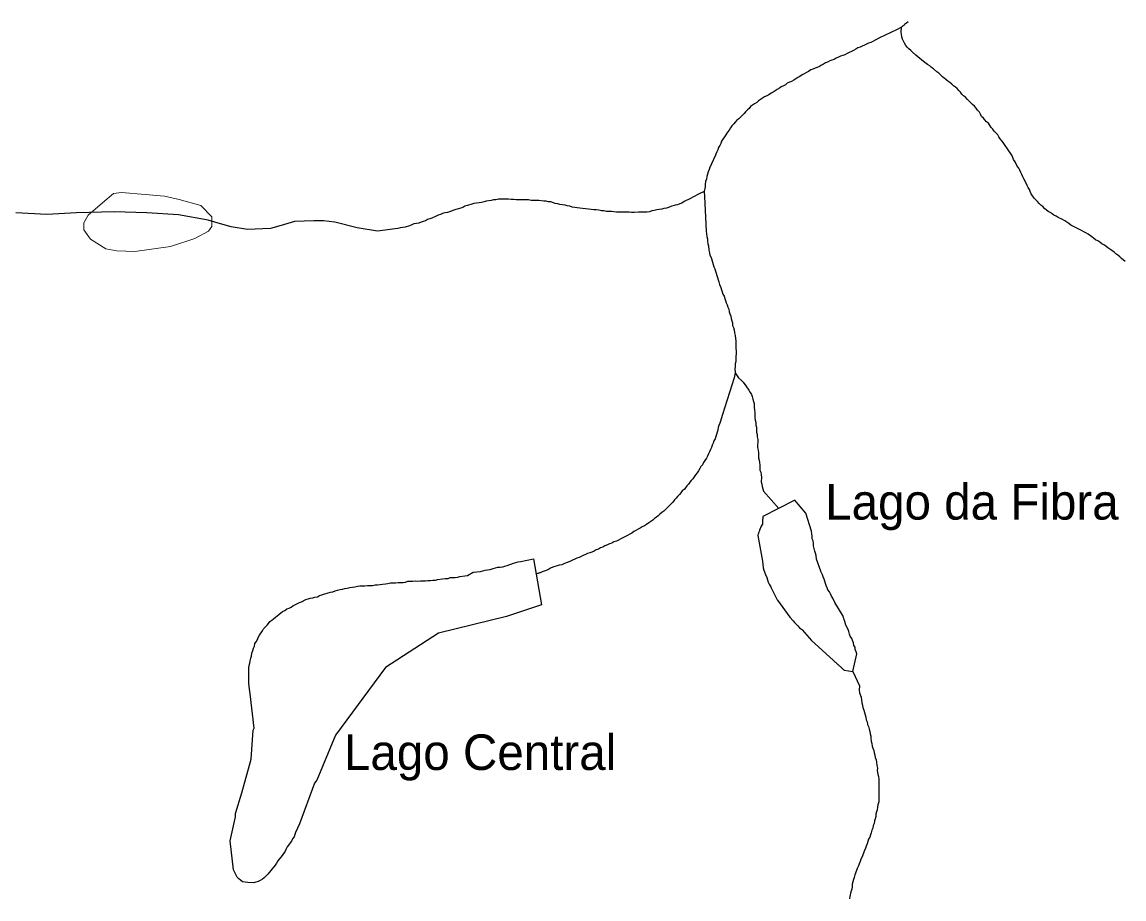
# Model space of a CAD drawing. Extents: x 785.9 to 812.4, y 7674.9 to 7703.1.
# Drawn here: x 791.421 to 793.899, y 7678.493 to 7680.465 of the extents above; entities that cross this region are included whole.
import ezdxf

# ---------------------------------------------------------------- set-up
doc = ezdxf.new("R2010")
doc.units = 0
doc.header["$LTSCALE"] = 0.04
doc.linetypes.add('LONG_DASHED', pattern=[7.5, 6, -1.5])
doc.linetypes.add('SHORT_DASHED', pattern=[2.7, 1.5, -1.2])
for name, color, linetype, lineweight in [('2', 7, 'Continuous', 25), ('21', 7, 'SHORT_DASHED', 13), ('3', 7, 'LONG_DASHED', 25), ('7', 7, 'Continuous', 25)]:
    doc.layers.add(name, color=color, linetype=linetype, lineweight=lineweight)
doc.layers.add('61', color=7, linetype='Continuous')

msp = doc.modelspace()

# ---------------------------------------------------------------- linework, layer by layer
at = {"layer": '2'}
msp.add_line((792.5718, 7679.2584), (792.5898, 7679.1547), dxfattribs=at)
for points in [[(791.94, 7679.0524), (791.9416, 7679.0573), (791.9441, 7679.0621), (791.9449, 7679.0678), (791.9481, 7679.0718), (791.9505, 7679.0767), (791.9522, 7679.0815), (791.9554, 7679.0864), (791.9619, 7679.0961), (791.9643, 7679.101), (791.9724, 7679.109), (791.9756, 7679.1131), (791.9789, 7679.1171), (791.9829, 7679.1204), (791.987, 7679.1236), (791.991, 7679.1268), (791.9991, 7679.1333), (792.0031, 7679.1366), (792.0072, 7679.1398), (792.012, 7679.1422), (792.0169, 7679.1455), (792.0217, 7679.1471), (792.0266, 7679.1495), (792.0306, 7679.1527), (792.0452, 7679.16), (792.0501, 7679.1616), (792.0598, 7679.1665), (792.0646, 7679.1681), (792.0695, 7679.1697), (792.0751, 7679.1705), (792.08, 7679.1722), (792.0857, 7679.173), (792.0905, 7679.1754), (792.0954, 7679.177), (792.1002, 7679.1786), (792.1099, 7679.1819), (792.1148, 7679.1835), (792.1205, 7679.1843), (792.1253, 7679.1859), (792.131, 7679.1875), (792.1366, 7679.1891), (792.1423, 7679.19), (792.1472, 7679.1916), (792.1528, 7679.1924), (792.1585, 7679.194), (792.1642, 7679.1948), (792.1698, 7679.1956), (792.1755, 7679.1964), (792.1811, 7679.1972), (792.1925, 7679.1972), (792.1981, 7679.1981), (792.2095, 7679.1981), (792.2151, 7679.1997), (792.2208, 7679.1997), (792.2265, 7679.2005), (792.2321, 7679.2013), (792.2386, 7679.2021), (792.2443, 7679.2029), (792.2499, 7679.2045), (792.2612, 7679.2045), (792.2669, 7679.2053), (792.2782, 7679.2053), (792.2839, 7679.2061), (792.2888, 7679.2078), (792.3001, 7679.2078), (792.3058, 7679.2086), (792.3114, 7679.2078), (792.3171, 7679.2086), (792.3284, 7679.2086), (792.3341, 7679.2094), (792.3397, 7679.2094), (792.3454, 7679.2102), (792.3511, 7679.2102), (792.3559, 7679.2118), (792.3672, 7679.2134), (792.3729, 7679.2142), (792.3794, 7679.2142), (792.3842, 7679.2159), (792.3956, 7679.2159), (792.4012, 7679.2167), (792.4061, 7679.2183), (792.4174, 7679.2199), (792.4231, 7679.2207), (792.4359, 7679.2281), (792.4522, 7679.2296), (792.4579, 7679.2312), (792.4627, 7679.2328), (792.4684, 7679.2337), (792.4741, 7679.2345), (792.4805, 7679.2361), (792.4862, 7679.2377), (792.491, 7679.2393), (792.4967, 7679.2393), (792.5024, 7679.2401), (792.5072, 7679.2417), (792.5121, 7679.2434), (792.5266, 7679.2482), (792.5315, 7679.2498), (792.5372, 7679.2515), (792.5428, 7679.2523), (792.5718, 7679.2584)], [(792.5898, 7679.1547), (792.5667, 7679.1476), (792.5667, 7679.1476), (792.5105, 7679.1288), (792.5105, 7679.1288), (792.3582, 7679.0913), (792.3582, 7679.0913), (792.2387, 7679.0139), (792.2387, 7679.0139), (792.1262, 7678.8614), (792.1262, 7678.8614), (792.084, 7678.7605), (792.0793, 7678.7535), (792.0452, 7678.6624)], [(791.9344, 7678.9545), (791.9327, 7678.965), (791.9311, 7678.9788), (791.9311, 7679.0128), (791.9319, 7679.0184), (791.9335, 7679.0233), (791.9344, 7679.0289), (791.936, 7679.0346), (791.9376, 7679.0395), (791.9384, 7679.0459), (791.94, 7679.0524)], [(791.8966, 7678.5588), (791.8966, 7678.5588), (791.8895, 7678.6244), (791.8895, 7678.6244), (791.9012, 7678.6784), (791.9012, 7678.6854), (791.9153, 7678.7324), (791.9153, 7678.7324), (791.9364, 7678.8074), (791.9364, 7678.8074), (791.9411, 7678.8731), (791.9434, 7678.8778), (791.9344, 7678.9545)], [(792.0452, 7678.6624), (792.0363, 7678.643), (792.0347, 7678.6381), (792.0331, 7678.6333), (792.0298, 7678.6284), (792.0274, 7678.6236), (792.0242, 7678.6195), (792.0209, 7678.6147), (792.0177, 7678.6106), (792.0153, 7678.6058), (792.0128, 7678.6009), (792.0064, 7678.5912), (792.0031, 7678.5871), (791.9999, 7678.5831), (791.9967, 7678.5791), (791.9934, 7678.5742), (791.9902, 7678.5693), (791.9837, 7678.5613), (791.9805, 7678.5572), (791.9772, 7678.5532), (791.974, 7678.5491), (791.97, 7678.5451), (791.9659, 7678.541), (791.9619, 7678.5378), (791.957, 7678.5346), (791.9522, 7678.5329), (791.9473, 7678.5313), (791.9424, 7678.5297), (791.9294, 7678.5306), (791.9174, 7678.5321), (791.9125, 7678.5354), (791.9085, 7678.5386), (791.9052, 7678.5426), (791.8966, 7678.5588)]]:
    msp.add_lwpolyline(points, dxfattribs=at)
at = {"layer": '21'}
msp.add_lwpolyline([(791.6451, 7680.0816), (791.698, 7680.0771), (791.7415, 7680.0738), (791.7744, 7680.066), (791.8234, 7680.0526), (791.8479, 7680.027), (791.8479, 7680.0053), (791.8407, 7679.9947), (791.81, 7679.9785), (791.7554, 7679.9607), (791.6746, 7679.949), (791.6345, 7679.9507), (791.6094, 7679.9551), (791.5749, 7679.9768), (791.5604, 7679.998), (791.5604, 7680.0136), (791.5699, 7680.0309), (791.6022, 7680.0588), (791.6273, 7680.0799)], close=True, dxfattribs=at)
at = {"layer": '3'}
for points in [[(793.2194, 7679.227), (793.2186, 7679.2285), (793.2179, 7679.2299), (793.2177, 7679.2303), (793.2079, 7679.2571), (793.2071, 7679.266), (793.2055, 7679.2709), (793.2039, 7679.2757), (793.2031, 7679.2814), (793.2015, 7679.2871), (793.2015, 7679.2927), (793.2007, 7679.2984), (793.1982, 7679.3032), (793.1982, 7679.3089), (793.1974, 7679.3146), (793.1966, 7679.3202), (793.1837, 7679.3607), (793.1586, 7679.3906), (793.1592, 7679.3899), (793.1227, 7679.3713), (793.0871, 7679.3532), (793.0866, 7679.3421)], [(793.0866, 7679.3421), (793.0866, 7679.3364), (793.0833, 7679.3316), (793.0801, 7679.3227), (793.0795, 7679.3211), (793.079, 7679.3196), (793.0784, 7679.3181), (793.0779, 7679.3166), (793.0773, 7679.3151), (793.0768, 7679.3135), (793.0762, 7679.312), (793.0757, 7679.3105), (793.0866, 7679.2531)], [(793.0866, 7679.2531), (793.0882, 7679.2377), (793.0898, 7679.2328), (793.093, 7679.2231), (793.0963, 7679.2159), (793.0979, 7679.211), (793.0995, 7679.2061), (793.1019, 7679.2013), (793.1044, 7679.1964), (793.106, 7679.1932), (793.1197, 7679.1657), (793.1201, 7679.165)], [(793.1964, 7679.0746), (793.2452, 7679.0306), (793.2452, 7679.0306), (793.2464, 7679.0295), (793.2476, 7679.0284), (793.2488, 7679.0273), (793.25, 7679.0262), (793.2512, 7679.0251), (793.2524, 7679.0241), (793.2536, 7679.023), (793.2548, 7679.0219), (793.256, 7679.0208), (793.2572, 7679.0197), (793.2584, 7679.0186), (793.2596, 7679.0176), (793.2608, 7679.0165), (793.262, 7679.0154), (793.2632, 7679.0143), (793.2644, 7679.0132), (793.2656, 7679.0121), (793.2668, 7679.0111), (793.268, 7679.01), (793.2692, 7679.0089), (793.2704, 7679.0078), (793.2897, 7679.0047), (793.2897, 7679.0047), (793.2986, 7679.0443), (793.297, 7679.0492), (793.2953, 7679.054), (793.2953, 7679.0597), (793.2921, 7679.0637), (793.2913, 7679.0694), (793.2889, 7679.0743), (793.2872, 7679.0791), (793.284, 7679.084), (793.2824, 7679.0888), (793.2808, 7679.0945), (793.2792, 7679.0993), (793.2743, 7679.109), (793.2719, 7679.1171), (793.2711, 7679.1196), (793.2705, 7679.1211), (793.27, 7679.1226), (793.2695, 7679.1242), (793.269, 7679.1257), (793.2685, 7679.1272), (793.268, 7679.1288), (793.2679, 7679.1292), (793.2492, 7679.16), (793.2444, 7679.1697), (793.2419, 7679.1746), (793.2395, 7679.1794), (793.2371, 7679.1843), (793.2338, 7679.1883), (793.2322, 7679.1932), (793.2298, 7679.1981), (793.2282, 7679.2029), (793.2266, 7679.2078), (793.2249, 7679.2126), (793.2233, 7679.2175), (793.2217, 7679.2223), (793.2201, 7679.2256), (793.2194, 7679.227)], [(793.1201, 7679.165), (793.1481, 7679.1268), (793.1554, 7679.1188), (793.1586, 7679.1147), (793.1626, 7679.1115), (793.1659, 7679.1074), (793.1699, 7679.1034), (793.174, 7679.1001), (793.1757, 7679.0984)], [(793.1757, 7679.0984), (793.1757, 7679.0984), (793.1964, 7679.0746)]]:
    msp.add_lwpolyline(points, dxfattribs=at)
at = {"layer": '7'}
for p, q in [((793.3984, 7680.4425), (793.3994, 7680.454)), ((793.0251, 7679.6766), (793.0225, 7679.6654)), ((793.0251, 7679.6766), (793.0327, 7679.6655))]:
    msp.add_line(p, q, dxfattribs=at)
for points in [[(793.3882, 7680.448), (793.3495, 7680.4296), (793.3398, 7680.4247), (793.335, 7680.4215), (793.3301, 7680.419), (793.3253, 7680.4174), (793.3204, 7680.4158), (793.3156, 7680.4134), (793.3107, 7680.411), (793.3059, 7680.4085), (793.301, 7680.4069), (793.2961, 7680.4045), (793.2913, 7680.4012), (793.2864, 7680.3988), (793.2816, 7680.3964), (793.2767, 7680.3948), (793.2719, 7680.3915), (793.267, 7680.3899), (793.2622, 7680.3883), (793.2573, 7680.3859), (793.2525, 7680.3843), (793.2476, 7680.381), (793.2427, 7680.3794), (793.2379, 7680.3778), (793.233, 7680.3754), (793.2282, 7680.3737), (793.2241, 7680.3705), (793.2193, 7680.3681), (793.2144, 7680.3656), (793.2096, 7680.3632), (793.2047, 7680.3616), (793.1999, 7680.3592), (793.195, 7680.3576), (793.1901, 7680.3543), (793.1853, 7680.3519), (793.1804, 7680.3487), (793.1756, 7680.3462), (793.1707, 7680.343), (793.1659, 7680.3406), (793.1618, 7680.3373), (793.157, 7680.3349), (793.1521, 7680.3317), (793.1473, 7680.33), (793.1424, 7680.3276), (793.1384, 7680.3244), (793.1335, 7680.322), (793.1287, 7680.3195), (793.1246, 7680.3163)], [(793.3994, 7680.454), (793.3994, 7680.454), (793.3882, 7680.448)], [(793.4143, 7680.466), (793.4102, 7680.4627), (793.4062, 7680.4595), (793.4049, 7680.4585), (793.4037, 7680.4575), (793.4024, 7680.4565), (793.4011, 7680.4555), (793.3999, 7680.4545), (793.3994, 7680.454)], [(793.6311, 7680.1901), (793.6279, 7680.1941), (793.6247, 7680.1982), (793.6214, 7680.203), (793.6182, 7680.2071), (793.6158, 7680.2119), (793.6117, 7680.216), (793.6077, 7680.22), (793.6044, 7680.224), (793.6012, 7680.2281), (793.5947, 7680.2378), (793.5907, 7680.241), (793.5866, 7680.2451), (793.5834, 7680.2491), (793.5793, 7680.2532), (793.5769, 7680.258), (793.5745, 7680.2629), (793.5704, 7680.2669), (793.5672, 7680.2718), (793.5632, 7680.2758), (793.5591, 7680.2799), (793.547, 7680.292), (793.5429, 7680.2961), (793.5389, 7680.2993), (793.5348, 7680.3033), (793.5316, 7680.3074), (793.5284, 7680.3114), (793.5243, 7680.3155), (793.5203, 7680.3187), (793.5162, 7680.322), (793.5122, 7680.3252), (793.5081, 7680.3292), (793.5033, 7680.3325), (793.4992, 7680.3357), (793.4952, 7680.3389), (793.4911, 7680.3422), (793.4871, 7680.3462), (793.4831, 7680.3503), (793.479, 7680.3535), (793.4709, 7680.36), (793.4669, 7680.3632), (793.4628, 7680.3665), (793.458, 7680.3697), (793.4483, 7680.3762), (793.4442, 7680.3802), (793.4402, 7680.3834), (793.4313, 7680.3907), (793.424, 7680.3972), (793.4199, 7680.4012), (793.4159, 7680.4053), (793.4119, 7680.4085), (793.4086, 7680.4126), (793.4062, 7680.4174), (793.4038, 7680.4223), (793.4013, 7680.4271), (793.3997, 7680.432), (793.3989, 7680.4377), (793.3984, 7680.4425)], [(793.1246, 7680.3163), (793.1198, 7680.3139), (793.1149, 7680.3106), (793.1109, 7680.3074), (793.106, 7680.305), (793.1011, 7680.3017), (793.0963, 7680.2993), (793.0914, 7680.2969), (793.0866, 7680.2944), (793.0817, 7680.2912), (793.0777, 7680.288), (793.0736, 7680.2847), (793.0688, 7680.2815), (793.0639, 7680.2783), (793.0599, 7680.275), (793.0566, 7680.271), (793.0526, 7680.2677), (793.0485, 7680.2637), (793.0453, 7680.2596), (793.0413, 7680.2556), (793.0372, 7680.2516), (793.0332, 7680.2475), (793.0291, 7680.2443), (793.0251, 7680.2402), (793.0218, 7680.2362), (793.0178, 7680.2321), (793.0146, 7680.2273), (793.0113, 7680.2224), (793.0081, 7680.2176), (793.004, 7680.2119), (793.0008, 7680.2071), (792.9976, 7680.2022), (792.9943, 7680.1973), (792.9927, 7680.1925), (792.9903, 7680.1876), (792.9879, 7680.1828), (792.9862, 7680.1779), (792.9838, 7680.1731), (792.9814, 7680.1682), (792.9798, 7680.1634), (792.9773, 7680.1585), (792.9757, 7680.1536), (792.9725, 7680.1488), (792.9709, 7680.1439), (792.9684, 7680.1391), (792.9668, 7680.1334), (792.9644, 7680.1286), (792.9628, 7680.1229), (792.9612, 7680.118), (792.9603, 7680.1116), (792.9587, 7680.1067), (792.9579, 7680.1002), (792.9579, 7680.0946), (792.9555, 7680.0841)], [(793.9022, 7679.9271), (793.8941, 7679.9336), (793.8901, 7679.9376), (793.886, 7679.9408), (793.8812, 7679.9441), (793.8771, 7679.9481), (793.8723, 7679.9514), (793.8674, 7679.9546), (793.8634, 7679.9578), (793.8585, 7679.9611), (793.8545, 7679.9643), (793.8496, 7679.9667), (793.8456, 7679.97), (793.8407, 7679.9732), (793.8358, 7679.9756), (793.831, 7679.9789), (793.8269, 7679.9821), (793.8189, 7679.9886), (793.814, 7679.991), (793.8091, 7679.9934), (793.8043, 7679.9967), (793.78, 7680.0088), (793.7752, 7680.012), (793.7711, 7680.0153), (793.7663, 7680.0185), (793.7614, 7680.0209), (793.7517, 7680.0258), (793.7468, 7680.029), (793.742, 7680.0307), (793.7379, 7680.0339), (793.7339, 7680.0371), (793.729, 7680.0396), (793.7209, 7680.046), (793.7169, 7680.0501), (793.7129, 7680.0533), (793.7088, 7680.0574), (793.7048, 7680.0614), (793.7015, 7680.0655), (793.6975, 7680.0695), (793.691, 7680.0792), (793.6886, 7680.0841), (793.687, 7680.0889), (793.6837, 7680.093), (793.6821, 7680.0978), (793.6773, 7680.1075), (793.674, 7680.1124), (793.6724, 7680.1172), (793.67, 7680.1221), (793.6675, 7680.1269), (793.6651, 7680.1318), (793.6627, 7680.1367), (793.6594, 7680.1415), (793.6546, 7680.1512), (793.6514, 7680.1561), (793.6497, 7680.1609), (793.6473, 7680.1658), (793.6408, 7680.1755), (793.6376, 7680.1804), (793.6311, 7680.1901)], [(792.9443, 7680.0791), (792.9393, 7680.0768), (792.9345, 7680.0735), (792.9199, 7680.0663), (792.915, 7680.0638), (792.9102, 7680.0614), (792.9053, 7680.0582), (792.9005, 7680.0566), (792.8956, 7680.0541), (792.89, 7680.0533), (792.8802, 7680.0501), (792.8754, 7680.0485), (792.8705, 7680.0468), (792.8649, 7680.046), (792.86, 7680.0444), (792.8544, 7680.0436), (792.8487, 7680.0428), (792.843, 7680.0412), (792.8374, 7680.0404), (792.8325, 7680.0388), (792.8268, 7680.0379), (792.8074, 7680.0379), (792.7977, 7680.0371), (792.792, 7680.0371), (792.7864, 7680.0379), (792.7581, 7680.0379), (792.7524, 7680.0388), (792.7467, 7680.0396), (792.7354, 7680.0396), (792.7297, 7680.0404), (792.7241, 7680.0404), (792.7184, 7680.042), (792.7128, 7680.0428), (792.7071, 7680.0428), (792.7014, 7680.0436), (792.695, 7680.0444), (792.6885, 7680.0452), (792.682, 7680.046), (792.6755, 7680.0468), (792.6699, 7680.0477), (792.6642, 7680.0485), (792.6585, 7680.0493), (792.6529, 7680.0509), (792.6472, 7680.0517), (792.6424, 7680.0533), (792.6367, 7680.0541), (792.631, 7680.0549), (792.6262, 7680.0566), (792.6205, 7680.0574), (792.6108, 7680.0606), (792.6051, 7680.0606), (792.6003, 7680.0622), (792.5946, 7680.0622), (792.5833, 7680.0638), (792.5663, 7680.0638), (792.5606, 7680.0655), (792.5323, 7680.0655), (792.5266, 7680.0663), (792.521, 7680.0663), (792.5153, 7680.0671), (792.4927, 7680.0671), (792.487, 7680.0655), (792.4813, 7680.0655), (792.4765, 7680.0638), (792.4652, 7680.0622), (792.4603, 7680.0606), (792.4546, 7680.0598), (792.449, 7680.059), (792.4433, 7680.0582), (792.4376, 7680.0574), (792.4328, 7680.0557), (792.4231, 7680.0525), (792.4174, 7680.0509), (792.4126, 7680.0485), (792.4028, 7680.0452), (792.3972, 7680.0436), (792.3923, 7680.042), (792.3826, 7680.0388), (792.3778, 7680.0371), (792.3721, 7680.0363), (792.3672, 7680.0347), (792.3624, 7680.0323), (792.3575, 7680.0307), (792.3527, 7680.029), (792.343, 7680.0242), (792.3381, 7680.0226), (792.3333, 7680.0209), (792.3284, 7680.0185), (792.3236, 7680.0169), (792.3187, 7680.0153), (792.3138, 7680.0129), (792.3082, 7680.012), (792.3025, 7680.0112), (792.2977, 7680.0096), (792.2928, 7680.0072), (792.2831, 7680.004), (792.2774, 7680.0031), (792.2718, 7680.0023), (792.2661, 7680.0007), (792.2604, 7679.9999), (792.2204, 7679.9952)], [(792.9555, 7680.0841), (792.9555, 7680.0841), (792.9443, 7680.0791)], [(792.9555, 7680.0841), (792.9555, 7680.0841), (792.956, 7680.0731)], [(792.956, 7680.0731), (792.9595, 7679.9951), (792.9612, 7679.9829), (792.9628, 7679.9781), (792.9628, 7679.9724), (792.9636, 7679.9667), (792.9652, 7679.9619), (792.966, 7679.9522), (792.9676, 7679.9465), (792.9684, 7679.9408), (792.9709, 7679.936), (792.9725, 7679.9303), (792.9741, 7679.9255), (792.9757, 7679.9198), (792.9773, 7679.915), (792.979, 7679.9101), (792.9806, 7679.9052), (792.9822, 7679.9004), (792.9838, 7679.8955), (792.9854, 7679.8907), (792.9871, 7679.8858), (792.9887, 7679.881), (792.9895, 7679.8753), (792.9927, 7679.868), (792.9943, 7679.8632), (792.996, 7679.8583), (792.9976, 7679.8535), (793, 7679.8486), (793.0016, 7679.8437), (793.0032, 7679.8389), (793.0049, 7679.834), (793.0073, 7679.8292), (793.0089, 7679.8243), (793.0105, 7679.8195), (793.0113, 7679.8138), (793.0129, 7679.809), (793.0154, 7679.8041), (793.0162, 7679.7984), (793.0178, 7679.7936), (793.0194, 7679.7887), (793.0194, 7679.7831), (793.021, 7679.7782), (793.0227, 7679.7734), (793.0235, 7679.7661), (793.0251, 7679.7604), (793.0259, 7679.7539), (793.0267, 7679.7483), (793.0267, 7679.7426)], [(792.2204, 7679.9952), (792.1747, 7680.0025), (792.1251, 7680.0153), (792.0995, 7680.0186), (792.0772, 7680.0186), (792.0343, 7680.0164), (792.0037, 7680.0075), (791.9803, 7680.0008), (791.9284, 7679.9986), (791.8917, 7680.0047), (791.8621, 7680.013), (791.8398, 7680.0197), (791.7735, 7680.0314), (791.7022, 7680.0364), (791.6286, 7680.0387), (791.5439, 7680.0364), (791.4771, 7680.0325), (791.4076, 7680.0363)], [(793.0267, 7679.7426), (793.0267, 7679.7369), (793.0267, 7679.7313), (793.0275, 7679.7256), (793.0275, 7679.7199), (793.0267, 7679.7135), (793.0267, 7679.7078), (793.0267, 7679.7021), (793.0251, 7679.6965), (793.0251, 7679.6908), (793.0243, 7679.6852), (793.0251, 7679.6787), (793.0251, 7679.6766)], [(793.0225, 7679.6654), (792.9968, 7679.5824), (792.9935, 7679.5727), (792.9919, 7679.5678), (792.9903, 7679.563), (792.9887, 7679.5581), (792.9871, 7679.5533), (792.9862, 7679.5476), (792.9846, 7679.5427), (792.983, 7679.5379), (792.9814, 7679.533), (792.9798, 7679.5282), (792.9773, 7679.5233), (792.9757, 7679.5185), (792.9733, 7679.5136), (792.9717, 7679.5088), (792.9693, 7679.5039), (792.9676, 7679.4991), (792.9652, 7679.4942), (792.9628, 7679.4893), (792.9603, 7679.4845), (792.9571, 7679.4796), (792.9539, 7679.4748), (792.9514, 7679.4699), (792.9482, 7679.4659), (792.9458, 7679.461), (792.9425, 7679.4562), (792.9393, 7679.4513), (792.9361, 7679.4473), (792.9328, 7679.4424), (792.9296, 7679.4384), (792.9264, 7679.4343), (792.9231, 7679.4303), (792.9199, 7679.4262), (792.9167, 7679.4222), (792.9134, 7679.4181), (792.9102, 7679.4141), (792.9061, 7679.4109), (792.9029, 7679.4068), (792.8997, 7679.4028), (792.8956, 7679.3987), (792.8924, 7679.3947), (792.8883, 7679.3906), (792.8851, 7679.3858), (792.8811, 7679.3817), (792.877, 7679.3777), (792.873, 7679.3736), (792.8689, 7679.3696), (792.8649, 7679.3655), (792.86, 7679.3623), (792.856, 7679.3583), (792.8519, 7679.355), (792.8479, 7679.3518), (792.8438, 7679.3486), (792.8398, 7679.3453), (792.8357, 7679.3421), (792.8309, 7679.3388), (792.826, 7679.3356), (792.8212, 7679.3324), (792.8163, 7679.3299), (792.8115, 7679.3275), (792.8066, 7679.3251), (792.8018, 7679.3218), (792.7969, 7679.3194), (792.7929, 7679.3162), (792.788, 7679.3138), (792.7831, 7679.3105), (792.7783, 7679.3081), (792.7726, 7679.3057), (792.7678, 7679.3032), (792.7629, 7679.3), (792.7581, 7679.2976), (792.7524, 7679.2968), (792.7475, 7679.2935), (792.7427, 7679.2919), (792.7378, 7679.2895), (792.7322, 7679.2871), (792.7273, 7679.2846), (792.7225, 7679.283), (792.7176, 7679.2798), (792.7128, 7679.2782), (792.7079, 7679.2757), (792.703, 7679.2733), (792.6982, 7679.2717), (792.6933, 7679.2701), (792.6885, 7679.2676), (792.6836, 7679.266), (792.6788, 7679.2636), (792.6739, 7679.2612)], [(793.0327, 7679.6655), (793.0396, 7679.6593), (793.0429, 7679.6552), (793.0494, 7679.6471), (793.0558, 7679.6374), (793.0591, 7679.6326), (793.0615, 7679.6277), (793.0631, 7679.6229), (793.0647, 7679.6172), (793.0663, 7679.6123), (793.068, 7679.6075), (793.068, 7679.5986), (793.0688, 7679.5929), (793.0696, 7679.5872), (793.0696, 7679.5759), (793.0704, 7679.5703), (793.0712, 7679.5646), (793.0712, 7679.5589), (793.0728, 7679.5541), (793.0728, 7679.5427), (793.0744, 7679.5379), (793.0744, 7679.5322), (793.0761, 7679.5266), (793.0761, 7679.5209), (793.0752, 7679.5144), (793.0752, 7679.5088), (793.0769, 7679.5023), (793.0777, 7679.4966), (793.0777, 7679.4853), (793.0793, 7679.4804), (793.0801, 7679.4748), (793.0809, 7679.4691), (793.0809, 7679.4578), (793.0825, 7679.4529), (793.0833, 7679.4473), (793.0841, 7679.4416), (793.0833, 7679.4311), (793.085, 7679.4262), (793.0858, 7679.4206), (793.0874, 7679.4157), (793.089, 7679.41), (793.1235, 7679.3717)], [(792.6739, 7679.2612), (792.6691, 7679.2595), (792.6642, 7679.2571), (792.6593, 7679.2555), (792.6545, 7679.2531), (792.6496, 7679.2506), (792.6448, 7679.249), (792.6399, 7679.2466), (792.6351, 7679.245), (792.6294, 7679.2442), (792.6246, 7679.2426), (792.6197, 7679.2409), (792.6148, 7679.2393), (792.61, 7679.2369), (792.6051, 7679.2345), (792.6003, 7679.232), (792.5914, 7679.2288), (792.5899, 7679.2282), (792.5883, 7679.2277), (792.5868, 7679.2271), (792.5853, 7679.2266), (792.5838, 7679.226), (792.5823, 7679.2255), (792.5807, 7679.2249), (792.5778, 7679.2238)], [(793.2897, 7679.0047), (793.305, 7678.9723), (793.3042, 7678.9626), (793.305, 7678.9569), (793.3083, 7678.9472), (793.3099, 7678.9343), (793.3115, 7678.9294), (793.3123, 7678.9238), (793.3148, 7678.9181), (793.3156, 7678.9124), (793.3172, 7678.9076), (793.3188, 7678.9019), (793.3196, 7678.8962), (793.322, 7678.8914), (793.3228, 7678.8857), (793.3253, 7678.8809), (793.3261, 7678.8752), (793.3277, 7678.8703), (793.3285, 7678.8647), (793.3301, 7678.8598), (793.3301, 7678.8542), (793.3309, 7678.8485), (793.3326, 7678.8428), (793.3334, 7678.8372), (793.335, 7678.8323), (793.3366, 7678.8275), (793.3374, 7678.8218), (793.339, 7678.8169), (793.3398, 7678.8113), (793.3423, 7678.8064), (793.3431, 7678.8008), (793.3439, 7678.7935), (793.3455, 7678.7878), (793.3447, 7678.7822), (793.3463, 7678.7741), (793.3471, 7678.7684), (793.3479, 7678.7627), (793.3479, 7678.7118), (793.3463, 7678.7053), (793.3455, 7678.6996), (793.3447, 7678.694), (793.3431, 7678.6891), (793.3415, 7678.6842), (793.3415, 7678.6786), (793.3398, 7678.6737), (793.3382, 7678.6689), (793.3374, 7678.6632), (793.3358, 7678.6584), (793.335, 7678.6527), (793.3326, 7678.6478), (793.3309, 7678.6422), (793.3293, 7678.6373), (793.3277, 7678.6325), (793.3253, 7678.6276), (793.3237, 7678.6227), (793.322, 7678.6171), (793.3196, 7678.6122), (793.318, 7678.6074), (793.3156, 7678.6025), (793.3123, 7678.5928), (793.3107, 7678.588), (793.3075, 7678.5831), (793.3059, 7678.5774), (793.3042, 7678.5726), (793.3026, 7678.5677), (793.2994, 7678.5621), (793.2978, 7678.5572), (793.2945, 7678.5475), (793.2929, 7678.5418), (793.2913, 7678.537), (793.2897, 7678.5321), (793.2881, 7678.5265), (793.2881, 7678.5208), (793.2872, 7678.5151), (793.2856, 7678.5095), (793.2832, 7678.499), (793.2821, 7678.4942), (793.2819, 7678.4934)]]:
    msp.add_lwpolyline(points, dxfattribs=at)

# ---------------------------------------------------------------- texts
at = {"layer": '61'}
for s, p in [('Lago da Fibra', (793.2275, 7679.3464)), ('Lago Central', (792.1452, 7678.7834))]:
    msp.add_text(s, height=0.08, dxfattribs=at).set_placement(p)

doc.saveas('drawing.dxf')
